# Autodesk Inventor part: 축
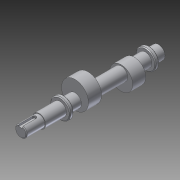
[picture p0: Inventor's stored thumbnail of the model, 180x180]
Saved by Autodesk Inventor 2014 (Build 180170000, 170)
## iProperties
Created: 2014-12
Part Number: 축
Material: 알루미늄 6061
Document SubType Name: Modeling
Designer: Owner
Density: 2.71 g/cm^3
Appearance: 알루미늄 - 평지
Mass: 182.114 g
Surface Area: 161.177 cm^2
Volume: 67.2007 cm^3
Author: Owner
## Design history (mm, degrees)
sketch "스케치1"
  geometry: L1 (-90, 0)-(90, 0); L2 (-90, 0)-(-90, 7.5); L3 (-90, 7.5)-(-66, 7.5); L4 (-66, 7.5)-(-66, 8.5); L5 (-66, 8.5)-(-39, 8.5); L6 (-39, 8.5)-(-39, 13); L7 (-39, 13)-(-34, 13); L8 (-34, 13)-(-34, 8.5); L9 (-34, 8.5)-(72, 8.5); L10 (72, 8.5)-(72, 13); L11 (72, 13)-(77, 13); L12 (77, 13)-(77, 8.5); L13 (77, 8.5)-(90, 8.5); L14 (90, 8.5)-(90, 0); 2 further points
  constraints: 28 end point, 10 parallel, 2 horizontal alignment, 2 perpendicular, 1 coincident, 1 horizontal, 1 midpoint, 1 vertical
  dimensions: "d0" = 180 distance of L1.start L1.end; "d1" = 15 diameter of L3 L1; "d2" = 17 diameter of L5 L1; "d3" = 26 diameter of L7 L1; "d4" = 26 diameter of L11 L1; "d5" = 24 distance of L2.end L3.end; "d6" = 27 distance of L4.end L5.end; "d7" = 5 distance of L6.end L7.end; "d8" = 13 distance of L12.end L13.end; "d9" = 5 distance of L10.end L11.end
revolve "회전1" sketch "스케치1" stored, may be unused: angle "d10" = 90 deg
node "작업 평면1"
sketch "스케치2"
  geometry: C1 r 17.5 at (0, 6); 1 further point
  constraints: 1 centre point, 1 vertical alignment
  dimensions: "d14" = 35 diameter of C1; "d15" = 6 distance of point (0, 0) C1.centre
extrude "돌출1" join sketch "스케치2" distance "d16" = 17; taper "d17" = 0 deg
node "작업 평면2"
sketch "스케치3"
  geometry: C1 r 15 at (0, -5); 1 further point
  constraints: 1 centre point, 1 vertical alignment
  dimensions: "d19" = 30 diameter of C1; "d20" = 5 distance of C1.centre point (0, 0)
extrude "돌출2" join sketch "스케치3" distance "d21" = 17; taper "d22" = 0 deg
node "작업 평면3"
sketch "스케치6"
  geometry: L1 (-12, -7.5)-(-12, 7.5) reference; L2 (-12, 2.5)-(5.5, 2.5); L3 (-12, -2.5)-(5.5, -2.5); L4 (-12, 2.5)-(-12, -2.5); A1 r 2.5 centre (5.5, 0) between (5.5, -2.5) and (5.5, 2.5); 2 further points
  constraints: 6 end point, 2 point on circle, 2 point on line, 1 centre point, 1 collinear, 1 midpoint, 1 parallel, 1 perpendicular
  dimensions: "d38" = 17.5 distance of L2.start L2.end; "d39" = 17.5 distance of L3.start L3.end; "d42" = 2.5 distance from line of L2 point (-12, 0); "d43" = 2.5 distance from line of L3 point (-12, 0); "d44" = 5 diameter of A1
extrude "돌출3" cut sketch "스케치6" distance "d45" = 3; taper "d46" = 0 deg
chamfer "모따기1" distance "d47" = 1; stored, may be unused: second distance "d48" = 2, angle "d49" = 45 deg
node "솔리드1"
other parameters: "d11" = -70.5, "d18" = -32.5
